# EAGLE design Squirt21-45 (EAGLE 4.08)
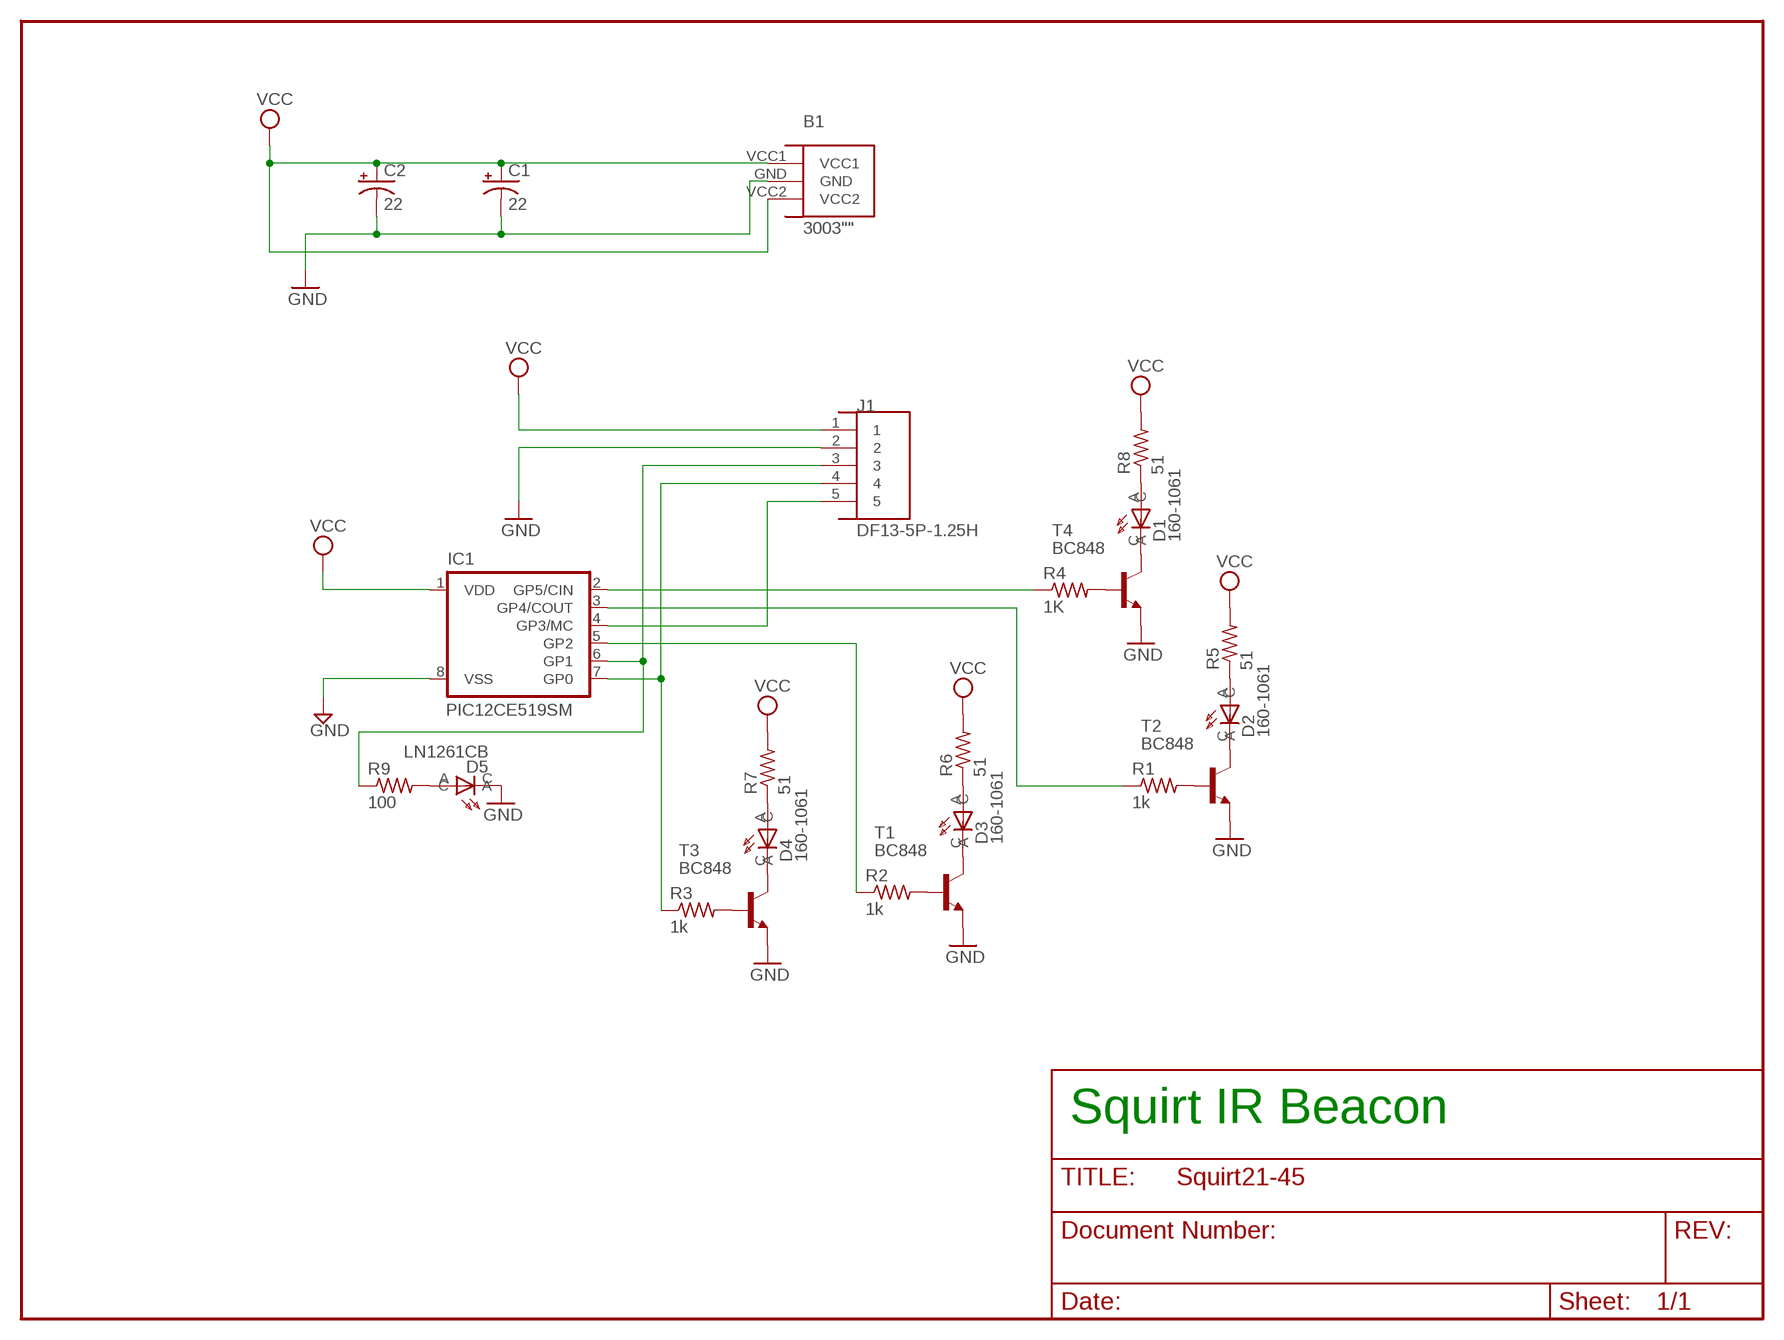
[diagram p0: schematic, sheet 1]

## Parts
B1  3003""  [3003]
C1  22  CPOL-USCT3528  [CT3528]
C2  22  CPOL-USCT3528  [CT3528]
D1  160-1061  [160-1061]
D2  160-1061  [160-1061]
D3  160-1061  [160-1061]
D4  160-1061  [160-1061]
D5  LN1261CB  [LN1_61CB]
IC1  PIC12CE519SM  [SO-08M]
J1  DF13-5P-1.25H  [DF13-5P-1.25H]
R1  1k  R-US_R0805  [R0805]
R2  1k  R-US_R0805  [R0805]
R3  1k  R-US_R0805  [R0805]
R4  1K  R-US_R0805  [R0805]
R5  51  R-US_R0805  [R0805]
R6  51  R-US_R0805  [R0805]
R7  51  R-US_R0805  [R0805]
R8  51  R-US_R0805  [R0805]
R9  100  R-US_R0805  [R0805]
T1  BC848  [SOT23]
T2  BC848  [SOT23]
T3  BC848  [SOT23]
T4  BC848  [SOT23]

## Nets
GND: B1.GND C1.- C2.- D5.C IC1.8(VSS) J1.2 T1.2(E) T2.2(E) T3.2(E) T4.2(E)
GP0: IC1.7(GP0) J1.4 R3.1
GP1: IC1.6(GP1) J1.3 R9.1
GP2: IC1.5(GP2) R2.1
GP3: IC1.4(GP3/MC) J1.5
GP4: IC1.3(GP4/COUT) R1.1
GP5: IC1.2(GP5/CIN) R4.1
N$1: D5.A R9.2
N$2: D1.A R8.1
N$3: R4.2 T4.1(B)
N$4: D2.A R5.1
N$5: D3.A R6.1
N$6: D4.A R7.1
N$7: R3.2 T3.1(B)
N$8: D4.C T3.3(C)
N$9: D3.C T1.3(C)
N$10: D2.C T2.3(C)
N$11: D1.C T4.3(C)
N$12: R2.2 T1.1(B)
N$17: R1.2 T2.1(B)
VCC: B1.VCC1 B1.VCC2 C1.+ C2.+ IC1.1(VDD) J1.1 R5.2 R6.2 R7.2 R8.2

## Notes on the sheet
- Squirt IR Beacon

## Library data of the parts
B1 = squirt21:3003: 20mm Coin Cell Holder
C1 C2 = rcl:CPOL-US: POLARIZED CAPACITOR, American symbol
D1-D4 = squirt21:160-1061: Infrared Emitting Diode
D5 = squirt21:LN1*61C: Surface Mount Chip LED (GW Type)
IC1 = microchip:PIC12C*?: MICROCONTROLLER
J1 = squirt21:DF13-5P-1.25: DF13 Series: 1.25 mm Pitch Compact Crimp Connector
R1-R9 = rcl:R-US_: RESISTOR, American symbol
T1-T4 = transistor-npn:BC848: NPN TRANSISTOR

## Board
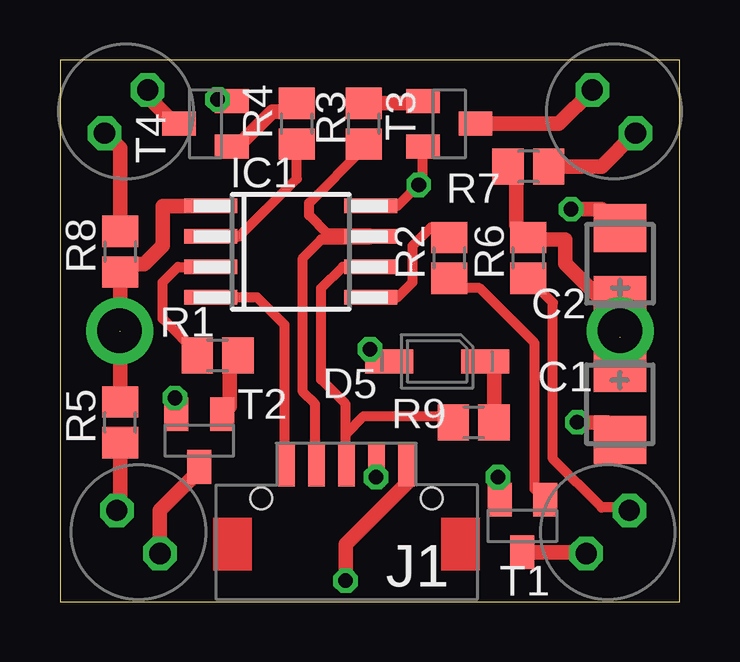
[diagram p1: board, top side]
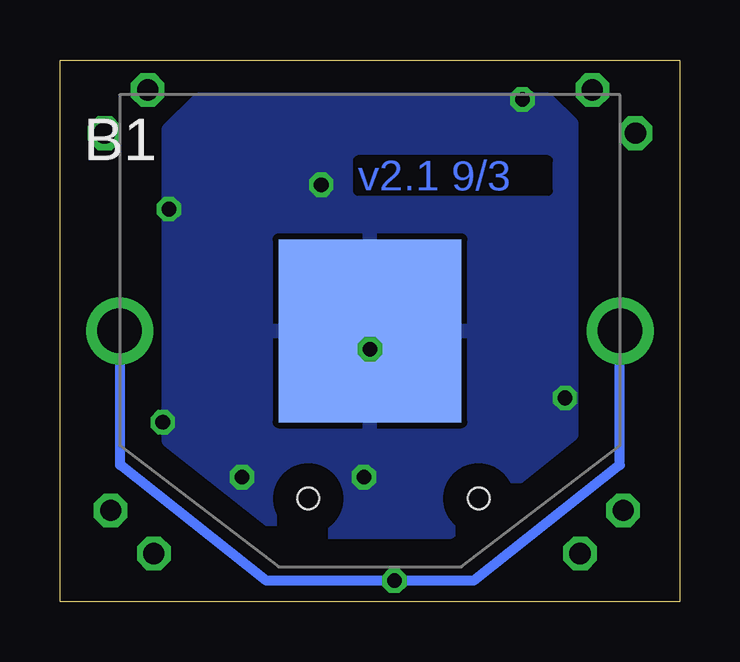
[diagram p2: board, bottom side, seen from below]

Size 25.83 x 22.6 mm. Coordinates in mm from the lower left corner, seen from the top.
Outline: 0,0 25.83,0 25.83,22.6 0,22.6 0,0
Copper layers used: Top, Bottom

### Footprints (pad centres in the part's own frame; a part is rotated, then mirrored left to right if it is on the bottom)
3003 = smd 7.62 x 7.62: GND 0,0 | drill 1.854 round: VCC1 -10.427,0; VCC2 10.427,0
CT3528 = smd 2 x 2.2: + -1.5,0; - 1.5,0
160-1061 = drill 0.889 octagon: A -0.898,0.898; C 0.898,-0.898
LN1_61CB = smd 2 x 1: A 2,0; C -2,0
SO-08M = smd 0.6 x 2.2: 1 -1.905,-3.33; 2 -0.635,-3.33; 3 0.635,-3.33; 4 1.905,-3.33; 5 1.905,3.33; 6 0.635,3.33; 7 -0.635,3.33; 8 -1.905,3.33
DF13-5P-1.25H = smd 0.7 x 1.8: 1 -2.54,-2.54; 2 -1.29,-2.54; 3 -0.04,-2.54; 4 1.21,-2.54; 5 2.46,-2.54 | hole 0.9: -3.59,-1.14; 3.51,-1.14
R0805 = smd 1.3 x 1.5: 1 -0.85,0; 2 0.85,0
SOT23 = smd 1 x 1.4: 1 -0.95,-1.1; 2 0.95,-1.1; 3 0,1.1

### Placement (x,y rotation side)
B1  12.92,11.3 0 bottom
C1  23.33,8.25 270 top
C2  23.33,14.09 90 top
D1  2.76,20.44 90 top
D2  3.26,2.92 0 top
D3  22.82,2.92 270 top
D4  23.08,20.44 180 top
D5  15.71,10.03 0 top
IC1  9.61,14.6 270 top
J1  11.9,3.17 180 top
R1  6.57,10.28 0 top
R2  16.22,14.35 270 top
R3  12.66,19.93 90 top
R4  9.87,19.93 90 top
R5  2.5,7.49 90 top
R6  19.52,14.35 90 top
R7  19.52,18.16 180 top
R8  2.5,14.6 270 top
R9  17.23,7.49 0 top
T1  19.27,3.17 180 top
T2  5.8,6.73 180 top
T3  16.22,19.93 270 top
T4  6.06,19.93 90 top

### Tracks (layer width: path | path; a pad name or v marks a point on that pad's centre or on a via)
GND  (via drill 0.61)
  Top 0.406: IC1.8 14.06,16.5 v14.95,17.39 15.12,17.56 T3.2
  Top 0.61: T2.2 4.85,8.5 v4.79,8.5 | v21.55,7.49 22.82,7.49 22.82,6.73 23.33,6.73 C1.- | D5.C 13.42,10.03 v12.92,10.54 | C2.- 23.33,15.62 22.57,16.38 v21.3,16.38 | T1.2 18.25,4.34 v18.25,5.2 | J1.2 13.17,5.71 v13.17,5.2 | T4.2 7.14,20.88 7.07,20.95 v6.57,20.95
  pour Bottom: 9.61,2.92 16.47,2.92 21.3,6.73 21.3,19.68 20.03,20.95 5.55,20.95 4.53,19.93 4.53,6.98
GP0
  Top 0.406: 12.41,15.11 12.92,15.11 12.94,15.14 IC1.7 12.92,15.26 12.92,15.36 11.14,15.36 10.38,16.12 10.38,16.63 12.66,18.92 R3.1 | 12.41,15.11 12.15,15.11 | 12.41,15.11 10.88,15.11 10.12,14.35 10.12,8.76 10.63,8.25 10.63,5.77 | J1.4 10.63,5.77 | 10.63,5.77 10.63,5.71
GP1
  Top 0.406: IC1.6 11.77,13.96 10.88,13.08 10.88,9.27 11.9,8.25 11.9,6.22 | R9.1 16.22,7.49 15.96,7.74 12.66,7.74 11.9,6.98 11.9,6.22 | J1.3 11.9,5.71 11.9,6.22
GP2
  Top 0.406: 16.22,15.11 R2.1 16.22,15.62 15.46,15.62 14.69,14.85 14.69,13.33 14.06,12.7 IC1.5
GP3
  Top 0.406: J1.5 9.36,5.71 9.36,11.55 8.22,12.7 IC1.4
GP4
  Top 0.406: IC1.3 4.91,13.96 4.28,13.33 4.28,11.81 5.8,10.28 R1.1
GP5
  Top 0.406: IC1.2 7.45,15.24 9.87,17.65 R4.1
N$1
  Top 0.61: R9.2 18.08,10.03 D5.A
N$2
  Top 0.61: D1.A 1.88,19.54 2.5,18.92 R8.1
N$3
  Top 0.61: T4.1 7.39,18.98 8.85,20.44 9.61,20.44 9.87,20.7 R4.2
N$4
  Top 0.61: D2.A 2.5,3.68 R5.1
N$5
  Top 0.406: R6.1 20.54,12.48 20.54,5.96 22.57,3.93 23.84,3.93 D3.A
N$6
  Top 0.61: D4.A 23.96,19.54 22.57,18.16 R7.1
N$7
  Top 0.61: T3.1 15.01,20.88 14.95,20.95 14.78,20.78 R3.2
N$8
  Top 0.61: 22.2,21.34 22.31,21.46 | 22.2,21.34 D4.C | T3.3 20.79,19.93 22.2,21.34
N$9
  Top 0.61: 22.06,2.02 22.06,1.9 | 22.06,2.02 D3.C | T1.3 22.06,2.07 22.06,2.02
N$10
  Top 0.61: T2.3 5.8,5.46 4.16,3.81 D2.C
N$11
  Top 0.61: T4.3 4.79,19.93 3.65,21.07 D1.C
N$12
  Top 0.406: R2.2 16.22,13.33 15.96,13.33 15.71,13.08 17.49,13.08 19.77,10.79 19.77,4.69 20.22,4.25 | 20.22,4.25 20.28,4.19 | T1.1 20.22,4.25
N$17
  Top 0.61: R1.2 7.16,10.03 7.07,10.03 7.07,8.15 T2.1
VCC  (via drill 0.61)  (2 unrouted)
  Top 0.61: 2.5,11.3 R8.2 2.5,14.09 3.52,14.09 4.28,14.85 4.28,16.5 IC1.1 | 2.5,8.25 R5.2 2.5,11.3 | 2.5,11.3 B1.VCC2 | 23.33,11.3 B1.VCC1 23.34,9.79 23.33,9.77 | 23.33,9.77 23.33,11.04 | 23.33,11.04 23.33,11.3 | 23.33,9.77 C1.+ 23.33,11.04 | R7.2 18.92,17.9 19.01,17.9 19.01,15.7 R6.2 19.77,15.2 19.77,15.11 21.04,15.11 21.04,14.12 22.59,12.57 23.33,12.57 | J1.1 14.44,4.95 11.9,2.41 v11.9,0.88 | 23.33,12.57 C2.+ | 23.33,11.3 23.33,12.57
  Bottom 0.406: 2.5,11.3 2.5,5.71 8.6,0.88 v11.9,0.88 17.23,0.88 23.33,5.71 23.33,11.02

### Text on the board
Bottom: v2.1 9/3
